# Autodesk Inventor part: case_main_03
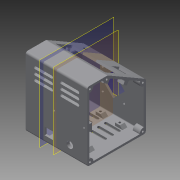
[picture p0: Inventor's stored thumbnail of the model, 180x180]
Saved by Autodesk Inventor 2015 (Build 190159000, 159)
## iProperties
Created: 2017-07
Part Number: case_main_03
Material: Generic
Document SubType Name: Modeling
Designer: jonas
Density: 1 g/cm^3
Appearance: Default
Author: jonas
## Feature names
1. Shape_main [Extrusion]
2. display_face [Chamfer]
3. outer_fillet [Fillet]
4. cut_inner_volume [Extrusion]
5. inner_fillet [Fillet]
6. cut_USB_12V [Extrusion]
7. vent_back_sweep
8. vent_bottom [Extrusion]
9. stepper_cut [Extrusion]
10. lcd_cut [Extrusion]
11. lcd_mount [Extrusion]
12. lcd_mount_chamfer [Chamfer]
13. Arduino_mount [Extrusion]
14. Arduino_holes [Hole]
15. 12V_jack [Extrusion]
16. power_board_mount [Extrusion]
17. power_board_holes [Hole]
18. Arduino&power_board_chamfer [Chamfer]
19. side_mount [Extrusion]
20. side_mount_holes [Hole]
21. side_mount_mirror [Mirror]
22. side_holder_chamfer [Chamfer]
23. Chamfer12
24. Chamfer13
25. switch_cut [Extrusion]
26. encoder_cut [Extrusion]
27. encoder_fix_cut [Extrusion]
28. lcd_screen_chamfer [Chamfer]
29. lcd_mount_fillets [Fillet]
30. missing_side_mount_hole [Hole]
31. Mirror3
32. USB_cut_fillet [Fillet]
33. vent_fillets [Fillet]
## Parameters: d0 = 89 mm, d3 = 85 mm, d4 = 0, d26 = 32 mm, d27 = 2 mm, d28 = 60 deg, d29 = 3 mm, d30 = 3 mm, d32 = 0, d35 = 1.25 mm, d49 = 0, d50 = 1 mm, d153 = 4 mm, d154 = 28 mm, d156 = 8 mm, d165 = 60 deg, d166 = 5 mm, d167 = 0, d168 = 0, d169 = 23 mm, d170 = 4 mm, d171 = 7 mm, d174 = 8 mm, d179 = 6 mm, d189 = 0, d231 = 3.5 mm, d233 = 0, d234 = 12 mm, d238 = 72 mm, d239 = 27.5 mm, d240 = 5 mm, d242 = 0, d257 = 2 mm, d258 = 2 mm, d260 = 2 mm, d261 = 2 mm, d262 = 45 deg, d263 = 5.9 mm, d264 = 5.9 mm, d266 = 0, d267 = 5.9 mm, d268 = 2 mm, d269 = 45 deg, d270 = 3.175 mm, d271 = 7 mm, d272 = 4 mm, d274 = 0, d275 = 3 mm, d276 = 6 mm, d277 = 4 mm, d278 = 2 mm, d279 = 90 deg, d281 = 118 deg, d282 = 2 mm, d284 = 0, d285 = 38 mm, d287 = 43 mm, d288 = 4 mm, d289 = 4 mm, d290 = 0, d291 = 45 deg, d292 = 3 mm, d293 = 6 mm, d294 = 4 mm, d295 = 2 mm, d296 = 90 deg, d298 = 118 deg, d299 = 4 mm, d300 = 2 mm, d301 = 45 deg, d302 = 6 mm, d303 = 2.5 mm, d305 = 0, d306 = 3 mm, d307 = 6 mm, d308 = 4 mm, d309 = 2 mm, d310 = 90 deg, d311 = 6 mm, d312 = 118 deg, d313 = 5.4 mm, d314 = 2 mm, d315 = 45 deg, d323 = 3.5 mm, d324 = 2 mm, d325 = 55 deg, d326 = 1 mm, d327 = 2 mm, d328 = 45 deg, d331 = 21 mm, d332 = 15 mm, d333 = 13 mm, d334 = 19.8 mm, d335 = 6 mm, d336 = 5 mm, d337 = 0, d338 = 16.8 mm, d339 = 8 mm, d340 = 5 mm, d341 = 0, d342 = 1 mm, d343 = 0, d344 = 1 mm, d345 = 2 mm, d346 = 45 deg, d348 = 3 mm, d349 = 2 mm, d350 = 3 mm, d351 = 2 mm, d352 = 1 mm, d353 = 1 mm, d354 = 1 mm, d355 = 1 mm, d356 = 2 mm, d357 = 4.15 mm, d358 = 4 mm, d359 = 3 mm, d360 = 6 mm, d361 = 4 mm, d362 = 2 mm, d363 = 90 deg, d364 = 6 mm, d365 = 118 deg, d366 = 0.5 mm, d367 = 0.5 mm
